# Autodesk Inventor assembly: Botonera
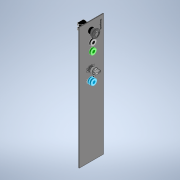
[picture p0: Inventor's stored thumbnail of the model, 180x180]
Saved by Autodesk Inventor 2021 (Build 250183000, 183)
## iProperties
Created: 2021-02
Part Number: Botonera
Material: Genérico
Document SubType Name: Assembly
Designer: ATOUZA
Author: ATOUZA
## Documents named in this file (5)
- D:\01 Paralaia\Grupos de Traballo\GT Maquetas\CAD 3D\E_Alimentación\Botonera.iam
- D:\01 Paralaia\Grupos de Traballo\GT Maquetas\CAD 3D\E_Alimentación\Placa botonera.ipt
- D:\01 Paralaia\Grupos de Traballo\GT Maquetas\CAD 3D\E_Alimentación\Pulsador XB5AA21\xb5_aa21.iam
- D:\01 Paralaia\Grupos de Traballo\GT Maquetas\CAD 3D\E_Alimentación\Selector XB5AD33\xb5_ad33.iam
- D:\01 Paralaia\Grupos de Traballo\GT Maquetas\CAD 3D\E_Alimentación\Seta XB5AS8445\xb5_as8445.iam
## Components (6 placed, 4 different names)
1. Placa botonera:1 — Coincidencia:1, Coincidencia:2, Coincidencia:3
2. xb5_aa21:1 [sub-assembly]
3. xb5_aa21:2 [sub-assembly] — Coincidencia:2
4. xb5_aa21:3 [sub-assembly] — Coincidencia:3
5. xb5_ad33:1 [sub-assembly]
6. xb5_as8445:1 [sub-assembly] — Coincidencia:1
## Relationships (3: Mate 3)
- Coincidencia:1 [Mate]: Placa botonera:1 ↔ xb5_as8445:1
- Coincidencia:2 [Mate]: Placa botonera:1 ↔ xb5_aa21:2
- Coincidencia:3 [Mate]: Placa botonera:1 ↔ xb5_aa21:3
